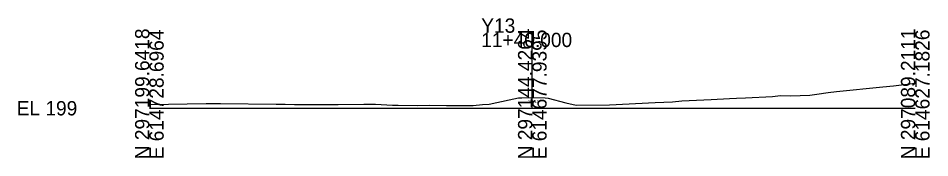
# Model space of a CAD drawing. Extents: x 517327 to 517505, y 114839 to 119364.
# Drawn here: x 517326.7 to 517505.2, y 114838.7 to 114866 of the extents above; entities that cross this region are included whole.
import ezdxf

# ---------------------------------------------------------------- set-up
doc = ezdxf.new("R2010")
doc.units = 0
for name, color, linetype in [('Exist XS Ground Line', 7, 'Continuous'), ('Old_Level_59', 7, 'Continuous'), ('Old_Level_63', 7, 'Continuous')]:
    doc.layers.add(name, color=color, linetype=linetype)

msp = doc.modelspace()

# ---------------------------------------------------------------- linework, layer by layer
at = {"layer": 'Exist XS Ground Line'}
for p, q in [((517498.08, 114852.78), (517502.36, 114853.29)), ((517483.06, 114851.09), (517485.31, 114851.44)), ((517485.31, 114851.44), (517486.96, 114851.63)), ((517486.96, 114851.63), (517496.02, 114852.54)), ((517496.02, 114852.54), (517498.08, 114852.78)), ((517418.93, 114849.18), (517422.85, 114850.04)), ((517422.85, 114850.04), (517424.65, 114850.39)), ((517424.65, 114850.39), (517425.29, 114850.41)), ((517425.29, 114850.41), (517427.57, 114850.48)), ((517427.57, 114850.48), (517429.87, 114850.39)), ((517429.87, 114850.39), (517430.49, 114850.36)), ((517430.49, 114850.36), (517433.94, 114849.41)), ((517433.94, 114849.41), (517435.93, 114848.94)), ((517442.45, 114849.05), (517451.4, 114849.51)), ((517451.4, 114849.51), (517454.82, 114849.65)), ((517454.82, 114849.65), (517456.64, 114849.83)), ((517456.64, 114849.83), (517462.37, 114850.06)), ((517462.37, 114850.06), (517465.97, 114850.27)), ((517465.97, 114850.27), (517467.38, 114850.35)), ((517467.38, 114850.35), (517469.09, 114850.42)), ((517469.09, 114850.42), (517474.37, 114850.67)), ((517474.37, 114850.67), (517476, 114850.83)), ((517476, 114850.83), (517477.89, 114850.79)), ((517477.89, 114850.79), (517479.79, 114850.84)), ((517479.79, 114850.84), (517481.7, 114850.91)), ((517481.7, 114850.91), (517483.06, 114851.09)), ((517352.36, 114849.07), (517363.45, 114849.26)), ((517363.45, 114849.26), (517365.2, 114849.3)), ((517365.2, 114849.3), (517365.67, 114849.29)), ((517365.67, 114849.29), (517366.3, 114849.31)), ((517366.3, 114849.31), (517377.19, 114849.13)), ((517377.19, 114849.13), (517378.98, 114849.13)), ((517378.98, 114849.13), (517380.75, 114849.11)), ((517380.75, 114849.11), (517385.22, 114849.12)), ((517385.22, 114849.12), (517389.36, 114849.12)), ((517389.36, 114849.12), (517394.38, 114849.19)), ((517394.38, 114849.19), (517396.65, 114849.18)), ((517396.65, 114849.18), (517399.95, 114848.95)), ((517399.95, 114848.95), (517401.09, 114848.97)), ((517401.09, 114848.97), (517404.8, 114848.89)), ((517404.8, 114848.89), (517407.29, 114848.96)), ((517407.29, 114848.96), (517410.58, 114848.93)), ((517410.58, 114848.93), (517413.79, 114848.9)), ((517413.79, 114848.9), (517415.79, 114848.89)), ((517415.79, 114848.89), (517417.59, 114849.12)), ((517417.59, 114849.12), (517418.93, 114849.18)), ((517435.93, 114848.94), (517442.45, 114849.05))]:
    msp.add_line(p, q, dxfattribs=at)
at = {"layer": 'Old_Level_63'}
for p, q in [((517427.36, 114848.36), (517427.36, 114863.14)), ((517352.36, 114848.36), (517427.36, 114848.36)), ((517427.36, 114848.36), (517502.36, 114848.36))]:
    msp.add_line(p, q, dxfattribs=at)

# ---------------------------------------------------------------- texts
at = {"layer": 'Old_Level_59'}
msp.add_text('201.11', height=0.5, dxfattribs=at).set_placement((517426.5, 114849.41))
at = {"layer": 'Old_Level_63'}
for s, p in [('Y13', (517417.36, 114863.14)), ('11+40.000', (517417.36, 114860.34)), ('EL 199', (517326.37, 114846.96))]:
    msp.add_text(s, height=2.8, dxfattribs=at).set_placement(p)
for s, p in [('N 297199.6418', (517352.36, 114838.37)), ('E 614728.6964', (517355.16, 114838.36)), ('N 297144.4264', (517427.36, 114838.36)), ('E 614677.9395', (517430.16, 114838.36)), ('N 297089.2111', (517502.36, 114838.37)), ('E 614627.1826', (517505.16, 114838.36))]:
    msp.add_text(s, height=2.8, rotation=90, dxfattribs=at).set_placement(p)

doc.saveas('drawing.dxf')
